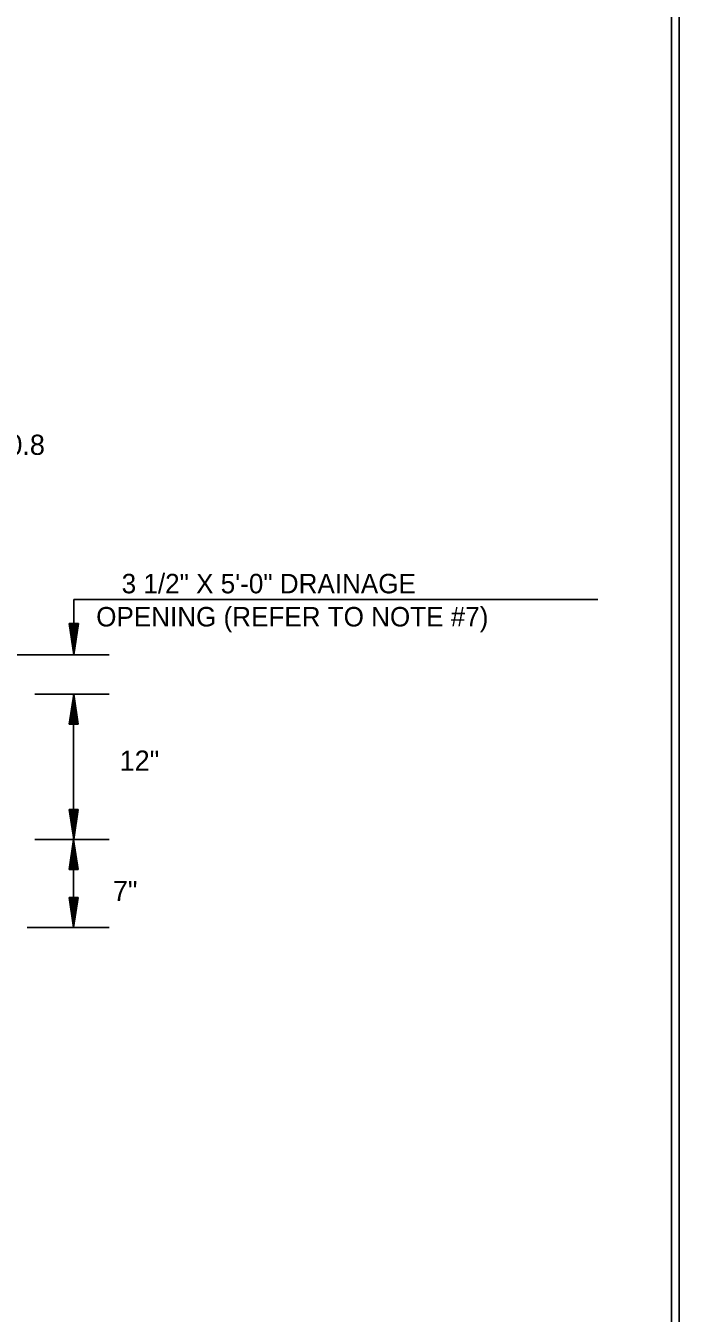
# Model space of a CAD drawing. Extents: x 714919 to 718439, y 1619644 to 1621844.
# Drawn here: x 718061 to 718397, y 1620261 to 1620922 of the extents above; entities that cross this region are included whole.
import ezdxf

# ---------------------------------------------------------------- set-up
doc = ezdxf.new("R2010")
doc.units = 0
for name, color, linetype in [('R_Annotation', 7, 'Continuous'), ('R_Border', 7, 'Continuous'), ('R_Dimension', 7, 'Continuous'), ('R_No Plot', 7, 'Continuous')]:
    doc.layers.add(name, color=color, linetype=linetype)

msp = doc.modelspace()

# ---------------------------------------------------------------- linework, layer by layer
at = {"layer": 'R_Border'}
msp.add_line((718392.98, 1619722.56), (718392.91, 1621777.16), dxfattribs=at)
at = {"layer": 'R_Dimension'}
for p, q in [((718086.08, 1620599.42), (718086.08, 1620627.82)), ((718086.08, 1620627.82), (718355.12, 1620627.82)), ((718083.67, 1620615.42), (718086.07, 1620599.42)), ((718088.47, 1620615.42), (718083.67, 1620615.42)), ((718084.07, 1620615.42), (718086.07, 1620602.09)), ((718084.48, 1620615.42), (718086.07, 1620604.84)), ((718084.88, 1620615.42), (718086.07, 1620607.51)), ((718085.29, 1620615.42), (718086.07, 1620610.22)), ((718085.7, 1620615.42), (718086.07, 1620612.89)), ((718088.47, 1620615.42), (718086.07, 1620599.42)), ((718086.85, 1620615.42), (718086.07, 1620610.22)), ((718087.67, 1620615.42), (718086.07, 1620604.84)), ((718088.07, 1620615.42), (718086.07, 1620602.09)), ((718087.27, 1620615.42), (718086.07, 1620607.51)), ((718086.45, 1620615.42), (718086.07, 1620612.89)), ((718104.37, 1620599.42), (717967.39, 1620599.42)), ((718104.37, 1620579.17), (718066.09, 1620579.17)), ((718083.74, 1620563.88), (718086.07, 1620579.17)), ((718084.17, 1620563.88), (718086.07, 1620576.67)), ((718086.05, 1620504.63), (718086.05, 1620579.17)), ((718088.32, 1620563.88), (718086.07, 1620579.17)), ((718087.97, 1620563.88), (718086.07, 1620576.67)), ((718084.52, 1620563.88), (718086.07, 1620573.99)), ((718084.86, 1620563.88), (718086.07, 1620571.48)), ((718085.3, 1620563.88), (718086.07, 1620568.89)), ((718087.54, 1620563.88), (718086.07, 1620573.99)), ((718087.2, 1620563.88), (718086.07, 1620571.48)), ((718086.85, 1620563.88), (718086.07, 1620568.89)), ((718083.74, 1620563.88), (718088.32, 1620563.88)), ((718085.64, 1620563.88), (718086.07, 1620566.3)), ((718086.42, 1620563.88), (718086.07, 1620566.3)), ((718083.83, 1620520.01), (718086.07, 1620504.64)), ((718088.41, 1620520.01), (718083.83, 1620520.01)), ((718084.17, 1620520.01), (718086.07, 1620507.23)), ((718084.61, 1620520.01), (718086.07, 1620509.91)), ((718084.95, 1620520.01), (718086.07, 1620512.41)), ((718085.3, 1620520.01), (718086.07, 1620515)), ((718085.73, 1620520.01), (718086.07, 1620517.51)), ((718088.41, 1620520.01), (718086.07, 1620504.64)), ((718086.85, 1620520.01), (718086.07, 1620515)), ((718087.63, 1620520.01), (718086.07, 1620509.91)), ((718087.97, 1620520.01), (718086.07, 1620507.23)), ((718087.28, 1620520.01), (718086.07, 1620512.41)), ((718086.51, 1620520.01), (718086.07, 1620517.51)), ((718104.37, 1620504.63), (718066.09, 1620504.63)), ((718083.71, 1620489.16), (718086.05, 1620504.63)), ((718084.08, 1620489.27), (718086.08, 1620502)), ((718088.31, 1620489.2), (718086.05, 1620504.63)), ((718087.87, 1620489.16), (718086.08, 1620502)), ((718084.45, 1620489.24), (718086.1, 1620499.36)), ((718084.94, 1620489.21), (718086.07, 1620496.8)), ((718086.05, 1620459.42), (718086.05, 1620498.77)), ((718087.14, 1620489.2), (718086.07, 1620496.8)), ((718087.57, 1620489.24), (718086.1, 1620499.36)), ((718083.71, 1620489.16), (718088.31, 1620489.2)), ((718085.25, 1620489.26), (718086.04, 1620494.23)), ((718085.61, 1620489.23), (718086, 1620491.66)), ((718086.41, 1620489.25), (718086, 1620491.66)), ((718086.78, 1620489.22), (718086.04, 1620494.23)), ((718088.35, 1620474.89), (718083.75, 1620474.84)), ((718083.75, 1620474.84), (718086.05, 1620459.42)), ((718084.18, 1620474.88), (718086.02, 1620462.05)), ((718084.49, 1620474.8), (718085.98, 1620464.68)), ((718084.92, 1620474.84), (718086.01, 1620467.25)), ((718085.28, 1620474.82), (718086.04, 1620469.82)), ((718085.65, 1620474.8), (718086.06, 1620472.39)), ((718087.61, 1620474.81), (718085.98, 1620464.68)), ((718087.12, 1620474.83), (718086.01, 1620467.25)), ((718087.97, 1620474.78), (718086.02, 1620462.05)), ((718086.81, 1620474.79), (718086.04, 1620469.82)), ((718088.35, 1620474.89), (718086.05, 1620459.42)), ((718086.45, 1620474.81), (718086.06, 1620472.39)), ((718104.37, 1620459.42), (718062.13, 1620459.42))]:
    msp.add_line(p, q, dxfattribs=at)
at = {"layer": 'R_No Plot'}
msp.add_lwpolyline([(715227.03, 1619717.36), (718396.93, 1619717.46), (718396.96, 1621782.56), (715226.86, 1621782.36)], close=True, dxfattribs=at)

# ---------------------------------------------------------------- texts
at = {"layer": 'R_Annotation'}
msp.add_text('ANGLE = 10.8', height=10.3685, dxfattribs=at).set_placement((717981.49, 1620702.02))
at = {"layer": 'R_Dimension'}
for s, height, p in [('3 1/2" X 5\'-0" DRAINAGE', 10, (718110.71, 1620630.96)), ('OPENING (REFER TO NOTE #7)', 10, (718097.63, 1620613.96)), ('12"', 10.369, (718109.66, 1620539.92)), ('7"', 10.369, (718106.18, 1620472.99))]:
    msp.add_text(s, height=height, dxfattribs=at).set_placement(p)

doc.saveas('drawing.dxf')
